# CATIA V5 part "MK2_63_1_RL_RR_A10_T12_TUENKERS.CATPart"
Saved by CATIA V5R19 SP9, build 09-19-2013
Part number: MK2_63_1_RL_RR_A10_T12_TUENKERS
Material "MISCHDICHTE": density 5043 kg/m3, Young's modulus 2e+11 Pa, Poisson ratio 0.266
Bounding box of the stored display mesh (mm): x -193.5 to 144, y -121.5 to 43, z -122.161 to 122.161
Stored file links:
  G:\Konstruktion\Modelle\Catia_V5\MK2_63_1_RL_RR_A10_T12_TUENKERS.CATPart
  G:\Konstruktion\Modelle\Catia_V5\Spannarme\SPANNARM_KPL_63_A10_217498_TUENKERS.CATPart
  C:\Catia\Tuenkers_B19SP9HF86_64\win_b64\reffiles\standard\MetricThickPitch.txt
  G:\Konstruktion\Modelle\Catia_V5\MK_63_1_A10_T12_TUENKERS.CATPart
  G:\Konstruktion\Modelle\Catia_V5\MK2_63_1_A40_T12_TUENKERS.CATPart
  G:\Konstruktion\Modelle\Catia_V5\V2_63_1_BR3_ZL_ZR_RL_RR_A40_T12_TUENKERS.CATPart
  HANDHEBEL_KPL_50_63_TUENKERS.CATPart
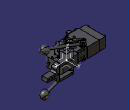
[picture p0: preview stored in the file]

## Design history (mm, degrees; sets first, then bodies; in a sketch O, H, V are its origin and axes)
AxisSystem1: origin (0, 0, 0), X (1, 0, 0), Y (0, 1, 0), Z (0, 0, 1)
Body1 (main body)
  Body2 "*DIT1\\*DIT2\\"
    Solid1: solid without history
  Assemble1: tool Body2
  Body3 "*DIT1\\*DIT3"
    Solid2 "Solid.1": solid without history
  Assemble2: tool Body3
  Body4 "*DIT1\\*DIT12\\*DIT16\\"
    Solid3 "Solid.1": solid without history
  Assemble3: tool Body4
  Body5 "*DIT1\\*DIT12\\*DIT17\\"
    Solid4 "Solid.1": solid without history
  Assemble4: tool Body5
  Body6 "*DIT1\\*DIT12\\MK_MK2_63_1_A10_A11_A12_T12_081112_3D_xSET4_2.1"
    Solid5 "Solid.1": solid without history
    Body7 "*DIT1\\*DIT12\\MK_MK2_63_1_A10_A11_A12_T12_081112_3D_xSET4_2.1\\Body.11 ( *SOL16 - wsp GEHAEUSE -  )"
      Solid6 "Solid.1": solid without history
    Add1 "*DIT1\\*DIT12\\MK_MK2_63_1_A10_A11_A12_T12_081112_3D_xSET4_2.1\\Body.11 ( *SOL16 - wsp GEHAEUSE -  )": tool Body7
    Body8 "*DIT1\\*DIT12\\MK_MK2_63_1_A10_A11_A12_T12_081112_3D_xSET4_2.1\\Body.12 ( *SOL17 - wsp GEHAEUSE -  )"
      Solid7 "Solid.1": solid without history
    Add2 "*DIT1\\*DIT12\\MK_MK2_63_1_A10_A11_A12_T12_081112_3D_xSET4_2.1\\Body.12 ( *SOL17 - wsp GEHAEUSE -  )": tool Body8
    Body9 "*DIT1\\*DIT12\\MK_MK2_63_1_A10_A11_A12_T12_081112_3D_xSET4_2.1\\Body.14 ( *SOL18 - wsp GEHAEUSE -  )"
      Solid8 "Solid.1": solid without history
    Add3 "*DIT1\\*DIT12\\MK_MK2_63_1_A10_A11_A12_T12_081112_3D_xSET4_2.1\\Body.14 ( *SOL18 - wsp GEHAEUSE -  )": tool Body9
  Assemble5: tool Body6
  Body10 "*DIT1\\MK_MK2_63_1_A10_A11_A12_T12_081112_3D_xSET2_1.1"
    Solid9 "Solid.1": solid without history
  Assemble6: tool Body10
  Rotate1: Axis edge [XY plane of AxisSystem1 | ZX plane of AxisSystem1], Angle 90, ToTransfor Assemble6
  Body11
    Body12 "*DIT1\\MK_MK2_63_1_A10_A11_A12_T12_081112_3D_xSET2_1.1\\Body.2 ( *SOL2 - wsp MK_MK2 63_1 -  )"
      Solid10 "Solid.1": solid without history
    Assemble7: tool Body12
    Body13 "*DIT1\\MK_MK2_63_1_A10_A11_A12_T12_081112_3D_xSET2_1.1\\Body.3 ( *SOL3 - wsp MK_MK2 63_1 -  )"
      Solid11 "Solid.1": solid without history
    Assemble8: tool Body13
    Body14 "*DIT1\\MK_MK2_63_1_A10_A11_A12_T12_081112_3D_xSET2_1.1\\Body.4 ( *SOL4 - wsp MK_MK2 63_1 -  )"
      Solid12 "Solid.1": solid without history
    Assemble9: tool Body14
    Body15 "*DIT1\\MK_MK2_63_1_A10_A11_A12_T12_081112_3D_xSET2_1.1\\Body.5 ( *SOL5 - wsp MK_MK2 63_1 -  )"
      Solid13 "Solid.1": solid without history
    Assemble10: tool Body15
    Body16 "*DIT1\\MK_MK2_63_1_A10_A11_A12_T12_081112_3D_xSET2_1.1\\Body.6 ( *SOL6 - wsp MK_MK2 63_1 -  )"
      Solid14 "Solid.1": solid without history
    Assemble11: tool Body16
    Rotate2: Axis edge, Angle 90, ToTransfor Assemble11
    Translate1: Direction edge [YZ plane of AxisSystem1 | XY plane of AxisSystem1], Length -1, ToTransfor Rotate2
  Assemble12: tool Body11
Body17 "Spannarm_kpl_63_A10_217498_Tuenkers", material "Steel"
  Sketch1 on xy-plane, origin (0, 0, 0), H (1, 0, 0), V (0, 1, 0)
    line L1 (43, 144) -> (15, 144)
    arc A1 centre (21.5, 11.6005) radius 20 from (35.6421, -2.5416) to (41.5, 11.6005) ccw
    line L2 (35.6421, -2.5416) -> (19.0919, -19.0919)
    line L3 (10.9602, 10.9602) -> (10.9602, -10.9602)
    line L4 (10.9602, 10.9602) -> (-10.9602, 10.9602)
    line L5 (-19.0919, 19.0919) -> (-10.9602, 10.9602)
    line L6 (10.6421, 48.8259) -> (-19.0919, 19.0919)
    line L7 (16.5, 62.968) -> (16.5, 78.0635)
    line L8 (43, 144) -> (43, 80)
    line L9 (10.9602, -10.9602) -> (19.0919, -19.0919)
    point P7 (10.9602, 10.9602)
    point P10 (-1.4396, 36.7442)
    point P11 (73, 37.6447)
    point P12 (45, 51.7188)
    reference intersected line E1 through (0, 0) direction (-0.7071, 0.7071)
    reference intersected line E2 through (0, 0) direction (-0.7071, 0.7071)
    reference intersected line E3 through (0, 0) direction (-0.7071, 0.7071)
    reference intersected line E4 through (0, 0) direction (0, 1) from yz-plane
    reference intersected line E5 through (0, 0) direction (-1, 0) from zx-plane
    line L10 (41.5, 78.0635) -> (41.5, 11.6005)
    line L11 (15, 80) -> (15, 144)
    arc A2 centre (-3.5, 62.968) radius 20 from (10.6421, 48.8259) to (16.5, 62.968) ccw
    arc A3 centre (14.5, 78.0635) radius 2 from (16.5, 78.0635) to (15, 80) ccw
    arc A4 centre (43.5, 78.0635) radius 2 from (41.5, 78.0635) to (43, 80) cw
    reference intersected line E6 through (0, 0) direction (0, 1) from yz-plane
    radius A1 = 20
    angle L4 L5 = 45
    distance P7 L2 = 27
    distance L2 L6 = 54
    angle L2 L9 = 90
    distance P7 E1 = 15.5
    distance E4 L3 = 10.9602
    distance E5 L1 = 144
    distance P10 L1 = 107.2558
    radius A4 = 2
    radius A3 = 2
    distance L10 L8 = 1.5
    distance L7 L10 = 25
    distance E6 L11 = 15
    distance L11 L7 = 1.5
    length L8 = 64
    radius A2 = 20
    length L11 = 64
    tangency: A1 L2, A1 L10, A4 L10, A2 L7, L6 A2, A3 L7
    coincidence: L9 E2, L5 E3, L6 P10
  Pad1: profile Sketch1, direction (0, 0, 1), length 39, opposite side length 39
  Chamfer1: length 0.1, angle 45, on edge [face of Pad1 from Sketch1.L3 | end face of Pad1]; edge [face of Pad1 from Sketch1.L4 | end face of Pad1]; edge [start face of Pad1 | face of Pad1 from Sketch1.L4]; edge [start face of Pad1 | face of Pad1 from Sketch1.L3]
  Sketch2 on face of Pad1 from Sketch1.L8, origin (43, 0, 0), H (0, 1, 0), V (0, 0, 1)
    line L1 (144, -10) -> (144, 10)
    line L2 (103, 10) -> (144, 10)
    arc A1 centre (103, 18) radius 8 from (103, 10) to (95, 18) cw
    line L3 (95, 24.9808) -> (95, 18)
    line L4 (-20, 39) -> (70, 39)
    line L5 (-20, 39) -> (-20, 28)
    line L6 (74, 28) -> (-20, 28)
    arc A2 centre (74, 22) radius 6 from (74, 28) to (80, 22) cw
    line L7 (80, 22) -> (80, -22)
    arc A3 centre (74, -22) radius 6 from (80, -22) to (74, -28) cw
    line L8 (-20, -28) -> (74, -28)
    line L9 (-20, -28) -> (-20, -39)
    line L10 (-20, -39) -> (70, -39)
    line L11 (95, -24.9808) -> (95, -18)
    arc A4 centre (103, -18) radius 8 from (95, -18) to (103, -10) cw
    line L12 (103, -10) -> (144, -10)
    reference intersected line E1 through (0, 0) direction (-1, 0) from xy-plane
    reference intersected line E2 through (0, 0) direction (0, 1) from zx-plane
    reference intersected line E3 through (0, 0) direction (0, 1) from zx-plane
    reference intersected line E4 through (0, 0) direction (0, 1) from zx-plane
    line L13 (-30, -44) -> (160, -44)
    line L14 (160, -44) -> (160, 44)
    line L15 (160, 44) -> (-30, 44)
    line L16 (-30, 44) -> (-30, -44)
    reference intersected line E5 through (0, 0) direction (-1, 0) from xy-plane
    reference intersected line E6 through (0, 0) direction (0, 1) from zx-plane
    line L17 (72.5882, -38.6593) -> (87.5882, -34.64)
    line L18 (87.5882, 34.64) -> (72.5882, 38.6593)
    arc A5 centre (85, 24.9808) radius 10 from (95, 24.9808) to (87.5882, 34.64) ccw
    arc A6 centre (70, 29) radius 10 from (72.5882, 38.6593) to (70, 39) ccw
    point P23 (70, 39)
    arc A7 centre (70, -29) radius 10 from (72.5882, -38.6593) to (70, -39) cw
    point P26 (70, -39)
    arc A8 centre (85, -24.9808) radius 10 from (95, -24.9808) to (87.5882, -34.64) cw
    distance L12 E1 = 10
    distance L12 L2 = 20
    distance L4 L10 = 78
    distance L6 L8 = 56
    distance L10 L12 = 29
    distance L8 L10 = 11
    radius A2 = 6
    radius A3 = 6
    radius A1 = 8
    radius A4 = 8
    distance L7 E2 = 80
    distance L3 E3 = 95
    distance L1 L5 = 164
    distance E4 L1 = 144
    distance L16 L14 = 190
    distance L15 L13 = 88
    distance L13 E5 = 44
    distance L14 E6 = 160
    angle L18 L4 = 15
    distance P23 L3 = 25
    radius A6 = 10
    radius A5 = 10
    angle L10 L17 = 15
    distance L11 P26 = 25
    radius A7 = 10
    radius A8 = 10
    tangency: L6 A2, A2 L7, L7 A3, A3 L8, L3 A1, A1 L2, A4 L12, A4 L11, A5 L3, A5 L18, A6 L18, A6 L4, A7 L17, A7 L10, A8 L11, A8 L17
    vertical: L1 V, L14 V, L16 V
    horizontal: L12 H, L13 H, L15 H
    coincidence: L5 L9, L11 L3
  Pocket1: profile Sketch2, direction (-1, 0, 0), length 95
  Sketch3 on face of Pad1 from Sketch1.L8, origin (43, 131.0889, -0.3784), H (0, 1, 0), V (0, 0, 1)
    point P1 (3.9111, 0.3784)
    reference intersected line E1 through (0, 0.3784) direction (-1, 0) from xy-plane
    reference intersected line E2 through (-131.0889, 0) direction (0, 1) from zx-plane
    reference intersected line E3 through (-131.0889, 0) direction (0, 1) from zx-plane
    reference intersected line E4 (12.9111, -38.6216) -> (-51.0889, -38.6216) from start face of Pad1
    distance P1 E2 = 135
    distance E3 E4 = 0
    coincidence: P1 E1
  Hole1: placed by Sketch3, at (43, 135, 0) direction (-1, 0, 0), diameter 6, through (limit type 6)
  Sketch4 on face of Pad1 from Sketch1.L8, origin (43, 113.9529, 0.5693), H (0, 1, 0), V (0, 0, 1)
    point P1 (-8.9529, -0.5693)
    reference projected point E1 (21.0471, -0.5693) from axis of face of Hole1
    reference intersected line E2 through (0, -0.5693) direction (-1, 0) from xy-plane
    distance P1 E1 = 30
    coincidence: P1 E2
  Hole2: placed by Sketch4, at (43, 105, 0) direction (-1, 0, 0), diameter 6, through (limit type 6)
  Sketch5 on face of Pad1 from Sketch1.L8, origin (43, 123.4122, -0.1089), H (0, 1, 0), V (0, 0, 1)
    point P1 (-3.4122, 0.1089)
    reference projected point E1 (11.5878, 0.1089) from axis of face of Hole1
    reference projected point E2 (-18.4122, 0.1089) from axis of face of Hole2
    distance P1 E1 = 15
    distance E2 P1 = 15
  Hole3: placed by Sketch5, at (43, 120, 0) direction (-1, 0, 0), diameter 9, through (limit type 6)
  Sketch6 on face of Pad1 from Sketch1.L8, origin (43, 93.5248, 1.4062), H (0, 1, 0), V (0, 0, 1)
    point P1 (-3.5248, -1.4062)
    reference projected point E1 (26.4752, -1.4062) from axis of face of Hole3
    reference projected point E2 (11.4752, -1.4062) from axis of face of Hole2
    distance P1 E1 = 30
    distance P1 E2 = 15
  Hole4: placed by Sketch6, at (43, 90, 0) direction (-1, 0, 0), diameter 9, through (limit type 6)
  Sketch7 on face of Pad1 from Sketch1.L9, origin (13.7879, -13.7879, 28.7565), H (0.7071, -0.7071, 0), V (0, 0, 1)
    point P1 (0.5009, 4.2435)
    reference intersected line E1 through (0, -28.7565) direction (-1, 0) from xy-plane
    reference projected line E2 (-19.4991, -67.7565) -> (-19.4991, 10.2435) from edge [face of Pad1 from Sketch1.L3 | face of Pad1 from Sketch1.L4]
    distance P1 E1 = 33
    distance E2 P1 = 20
  Hole5: placed by Sketch7, at (14.1421, -14.1421, 33) direction (0.7071, 0.7071, 0), diameter 6.647, depth 18, V-bottom angle 120, threaded "M8", thread diameter 8, thread depth 15, pitch 1.25
  RectPattern1: of Hole5, direction 1 instances 2, spacing 66, along edge [face of Pad1 from Sketch1.L3 | face of Pad1 from Sketch1.L4] reversed, direction 2 instances 2, spacing 40, along edge [face of Pad1 from Sketch1.L9 | face of Pocket1] reversed
  Sketch8 on face of Pocket1 from Sketch2.L6, origin (0, 0, 28), H (1, 0, 0), V (0, -1, 0)
    line L1 (19.0919, 19.0919) -> (35.6421, 2.5416)
    line L2 (36.7245, 1.3692) -> (-1.4142, -36.7696)
    line L3 (-1.4142, -36.7696) -> (-19.0919, -19.0919)
    line L4 (-19.0919, -19.0919) -> (-10.96, -10.96)
    line L5 (-10.96, -10.96) -> (10.96, -10.96)
    point P5 (10.96, -10.96)
    line L6 (10.96, -10.96) -> (10.96, 10.96)
    line L7 (10.96, 10.96) -> (19.0919, 19.0919)
    reference intersected line E1 through (0, 0) direction (0.7071, -0.7071)
    reference intersected line E2 through (0, 0) direction (0.7071, 0.7071)
    reference intersected line E3 through (0, 0) direction (0.7071, -0.7071)
    arc A1 centre (21.5, -11.6005) radius 20 from (35.6421, 2.5416) to (36.7245, 1.3692) cw
    reference intersected line E4 through (0, 0) direction (0, 1) from yz-plane
    distance E1 L1 = 27
    distance L3 L1 = 54
    distance L7 L2 = 25
    angle L6 L5 = 90
    radius A1 = 20
    length L2 = 53.9363
    distance E4 L6 = 10.96
    coincidence: E2 L7, L4 L7, P5 E3
    tangency: A1 L1
  Pad2: profile Sketch8, direction (0, 0, -1), length 1
  Mirror1: of Pad2, Sketch8, about xy-plane
  Body18 "KLEMMFLANSCH KPL"
    Sketch9 on xy-plane, origin (0, 0, 0), H (1, 0, 0), V (0, 1, 0)
      line L1 (-20.5061, 17.6777) -> (-31.1375, 7.0463)
      line L2 (-31.1375, 7.0463) -> (-19.1167, -4.9745)
      line L3 (-19.1167, -4.9745) -> (-25.4806, -11.3385)
      line L4 (-25.4806, -11.3385) -> (-11.3385, -25.4806)
      line L5 (-11.3385, -25.4806) -> (-4.9745, -19.1167)
      line L6 (-4.9745, -19.1167) -> (7.0463, -31.1375)
      line L7 (7.0463, -31.1375) -> (19.0671, -19.1167)
      line L8 (19.0671, -19.1167) -> (10.9106, -10.9602)
      line L9 (10.9106, -10.9602) -> (-10.9602, -10.9602)
      point P10 (-10.9602, -10.9602)
      line L10 (-10.9602, -10.9602) -> (-10.9602, 8.1317)
      line L11 (-10.9602, 8.1317) -> (-20.5061, 17.6777)
      reference intersected line E1 through (0, 0) direction (-0.7071, 0.7071)
      reference intersected line E2 through (0, 0) direction (-0.7071, 0.7071)
      reference intersected line E3 through (0, 0) direction (-0.7071, -0.7071)
      distance L4 L8 = 26
      distance L7 L5 = 17
      distance L5 L3 = 20
      distance L7 L1 = 54
      distance L4 L6 = 9
      distance E1 P10 = 15.5
      distance L11 E2 = 2
      distance L11 L8 = 1.965
      angle L11 L10 = 135
      angle L9 L8 = 45
      distance L7 P10 = 27
      distance E3 L7 = 27
      coincidence: L2 L6
    Pad3: profile Sketch9, direction (0, 0, 1), length 39, opposite side length -27
    Chamfer2: length 0.1, angle 45, on edge [face of Pad3 from Sketch9.L9 | end face of Pad3]; edge [face of Pad3 from Sketch9.L10 | end face of Pad3]
    Sketch10 on face of Pad3 from Sketch9.L6, origin (-12.0456, -12.0456, 0), H (0.7071, -0.7071, 0), V (0, 0, 1)
      circle A1 centre (20, 33) radius 4
      point P1 (20, 33)
      circle A2 centre (-20, 33) radius 4
      point P2 (-20, 33)
      reference projected line E1 (-27, 27) -> (-10, 27) from edge [start face of Pad3 | face of Pad3 from Sketch9.L2]
      reference projected line E2 (10, 27) -> (27, 27) from edge [start face of Pad3 | face of Pad3 from Sketch9.L6]
      reference projected line E3 (27, 27) -> (27, 39) from edge [face of Pad3 from Sketch9.L7 | face of Pad3 from Sketch9.L6]
      reference projected line E4 (-27, 27) -> (-27, 39) from edge [face of Pad3 from Sketch9.L2 | face of Pad3 from Sketch9.L1]
      radius A1 = 4
      radius A2 = 4
      distance E1 P2 = 6
      distance P1 E2 = 6
      distance E3 P1 = 7
      distance P2 E4 = 7
    Pad4: profile Sketch10, direction (0.7071, 0.7071, 0), length 20
    Sketch11 on face of Pad4, origin (-12.0456, -12.0456, 0), H (0.7071, -0.7071, 0), V (0, 0, 1)
      circle A1 centre (20, 33) radius 6.5
      point P1 (20, 33)
      circle A2 centre (-20, 33) radius 6.5
      point P2 (-20, 33)
      reference projected line E1 (-27, 27) -> (-27, 39) from edge [face of Pad3 from Sketch9.L2 | face of Pad3 from Sketch9.L1]
      reference projected line E2 (27, 27) -> (27, 39) from edge [face of Pad3 from Sketch9.L7 | face of Pad3 from Sketch9.L6]
      reference projected line E3 (-27, 27) -> (-10, 27) from edge [start face of Pad3 | face of Pad3 from Sketch9.L2]
      reference projected line E4 (10, 27) -> (27, 27) from edge [start face of Pad3 | face of Pad3 from Sketch9.L6]
      radius A1 = 6.5
      radius A2 = 6.5
      distance E1 P2 = 7
      distance E2 P1 = 7
      distance E3 P2 = 6
      distance E4 P1 = 6
    Pad5: profile Sketch11, direction (-0.7071, -0.7071, 0), length 1.4
    Chamfer3: length 0.1, angle 45, on edge [face of Pad5 from Sketch11.A1 | end face of Pad5]; edge [face of Pad5 from Sketch11.A2 | end face of Pad5]
    Sketch12 on end face of Pad5, origin (-13.0355, -13.0355, 0), H (0.7071, -0.7071, 0), V (0, 0, 1)
      circle A1 centre (20, 33) radius 6.5
      point P1 (20, 33)
      circle A2 centre (-20, 33) radius 6.5
      point P2 (-20, 33)
      reference projected line E1 (10, 27) -> (27, 27) from edge [start face of Pad3 | face of Pad4]
      reference projected line E2 (27, 27) -> (27, 39) from edge [face of Pad3 from Sketch9.L7 | face of Pad3 from Sketch9.L6]
      reference projected line E3 (-27, 27) -> (-27, 39) from edge [face of Pad3 from Sketch9.L2 | face of Pad3 from Sketch9.L1]
      reference projected line E4 (-27, 27) -> (-10, 27) from edge [start face of Pad3 | face of Pad4]
      radius A1 = 6.5
      radius A2 = 6.5
      distance E1 P1 = 6
      distance E2 P1 = 7
      distance E3 P2 = 7
      distance E4 P2 = 6
    Pad6: profile Sketch12, direction (-0.7071, -0.7071, 0), length 8
    Fillet1: radius 0.5, on end face of Pad6; edge [face of Pad6 from Sketch12.A1 | end face of Pad6]
    Mirror2: of the body so far, about xy-plane, deactivated
    Translate2: Direction edge [ZX plane of AxisSystem1 | YZ plane of AxisSystem1], Length -66, ToTransfor Mirror2
  Assemble13: tool Body18
  Rotate3: Axis edge [XY plane of AxisSystem1 | ZX plane of AxisSystem1], Angle 180, ToTransfor Assemble13
  Rotate4: Axis edge [ZX plane of AxisSystem1 | YZ plane of AxisSystem1], Angle 90, ToTransfor Rotate3
Body19 "ENDLAGENRASTE_LINKS"
  Solid15 "Manifold Solid #1213": solid without history
  Body20 "LUMP70"
    Solid16 "Manifold Solid #2778": solid without history
  Assemble14: tool Body20
  Body21 "LUMP73"
    Solid17 "Manifold Solid #4455": solid without history
  Assemble15: tool Body21
  Body22 "LUMP74"
    Solid18 "Manifold Solid #5598": solid without history
  Assemble16: tool Body22
  Body23 "LUMP76"
    Solid19 "Manifold Solid #7126": solid without history
  Assemble17: tool Body23
  Body24 "LUMP79"
    Solid20 "Manifold Solid #8329": solid without history
  Assemble18: tool Body24
  Body25 "LUMP81"
    Solid21 "Manifold Solid #8843": solid without history
  Assemble19: tool Body25
  Body26 "LUMP82"
    Solid22 "Manifold Solid #9252": solid without history
  Assemble20: tool Body26
  Body27 "LUMP85"
    Solid23 "Manifold Solid #10175": solid without history
  Assemble21: tool Body27
  Body28 "LUMP87"
    Solid24 "Manifold Solid #10993": solid without history
  Assemble22: tool Body28
  Body29 "LUMP88"
    Solid25 "Manifold Solid #11378": solid without history
  Assemble23: tool Body29
  Body30 "LUMP89"
    Solid26 "Manifold Solid #12146": solid without history
  Assemble24: tool Body30, deactivated
  Body31 "LUMP93"
    Solid27 "Manifold Solid #13965": solid without history
  Assemble25: tool Body31, deactivated
  Body32 "LUMP94"
    Solid28 "Manifold Solid #14222": solid without history
  Assemble26: tool Body32, deactivated
  Body33 "LUMP97"
    Solid29 "Manifold Solid #15145": solid without history
  Assemble27: tool Body33, deactivated
  Body34 "LUMP98"
    Solid30 "Manifold Solid #15554": solid without history
  Assemble28: tool Body34, deactivated
  Body35 "LUMP101"
    Solid31 "Manifold Solid #16781": solid without history
  Assemble29: tool Body35
  Body36 "LUMP102"
    Solid32 "Manifold Solid #17038": solid without history
  Assemble30: tool Body36
  Rotate5: Axis edge, Angle 90, ToTransfor Assemble30
Body37 "ENDLAGENRASTE_RECHTS"
  Body38 "LUMP69"
    Solid33 "Manifold Solid #2521": solid without history
  Assemble31: tool Body38
  Body39 "LUMP71"
    Solid34 "Manifold Solid #3035": solid without history
  Assemble32: tool Body39
  Body40 "LUMP72"
    Solid35 "Manifold Solid #3745": solid without history
  Assemble33: tool Body40
  Body41 "LUMP75"
    Solid36 "Manifold Solid #6741": solid without history
  Assemble34: tool Body41
  Body42 "LUMP77"
    Solid37 "Manifold Solid #7511": solid without history
  Assemble35: tool Body42
  Body43 "LUMP78"
    Solid38 "Manifold Solid #7920": solid without history
  Assemble36: tool Body43
  Body44 "LUMP80"
    Solid39 "Manifold Solid #8586": solid without history
  Assemble37: tool Body44
  Body45 "LUMP83"
    Solid40 "Manifold Solid #9661": solid without history
  Assemble38: tool Body45
  Body46 "LUMP84"
    Solid41 "Manifold Solid #9918": solid without history
  Assemble39: tool Body46
  Body47 "LUMP86"
    Solid42 "Manifold Solid #10584": solid without history
  Assemble40: tool Body47
  Body48 "LUMP90"
    Solid43 "Manifold Solid #12531": solid without history
  Assemble41: tool Body48
  Body49 "LUMP91"
    Solid44 "Manifold Solid #13299": solid without history
  Assemble42: tool Body49
  Body50 "LUMP92"
    Solid45 "Manifold Solid #13708": solid without history
  Assemble43: tool Body50
  Body51 "LUMP95"
    Solid46 "Manifold Solid #14479": solid without history
    Translate3: Direction edge [face of Solid44 | face of Solid44], Length -4, ToTransfor Solid46
  Assemble44: tool Body51
  Body52 "LUMP96"
    Solid47 "Manifold Solid #14736": solid without history
    Translate4: Direction edge [face of Solid44 | face of Solid44], Length -4, ToTransfor Solid47
  Assemble45: tool Body52
  Body53 "LUMP99"
    Solid48 "Manifold Solid #15963": solid without history
    Translate5: Direction edge [face of Solid44 | face of Solid44], Length -4, ToTransfor Solid48
  Assemble46: tool Body53
  Body54 "LUMP100"
    Solid49 "Manifold Solid #16372": solid without history
    Translate6: Direction edge [face of Solid44 | face of Solid44], Length -4, ToTransfor Solid49
  Assemble47: tool Body54
  Body55 "LUMP103"
    Solid50 "Manifold Solid #17295": solid without history
  Assemble48: tool Body55
  Rotate6: Axis edge, Angle 90, ToTransfor Assemble48
Body56 "Handhebel_KPL_218625_TUENKERS.1"
  Solid51: solid without history
  Body57 "Handhebel_KPL_218625_TUENKERS.2"
    Solid52: solid without history
  Assemble49: tool Body57
  Translate7: Direction edge [ZX plane of AxisSystem1 | YZ plane of AxisSystem1], ToTransfor Assemble49, Length 28
  Translate8: Direction edge [XY plane of AxisSystem1 | ZX plane of AxisSystem1], ToTransfor Translate7, Length -86
  Translate9: Direction edge [YZ plane of AxisSystem1 | XY plane of AxisSystem1], ToTransfor Translate8, Length -4
Body58 "Handhebel_KPL_218625_TUENKERS.1"
  Solid53: solid without history
  Body59 "Handhebel_KPL_218625_TUENKERS.2"
    Solid54: solid without history
  Assemble50: tool Body59
  Translate10: Direction edge [ZX plane of AxisSystem1 | YZ plane of AxisSystem1], Length 28, ToTransfor Assemble50
  Translate11: Direction edge [XY plane of AxisSystem1 | ZX plane of AxisSystem1], Length -86, ToTransfor Translate10
  Translate12: Direction edge [YZ plane of AxisSystem1 | XY plane of AxisSystem1], Length -4, ToTransfor Translate11
  Symmetry1: ToTransfor Translate12, Reference XY plane of AxisSystem1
